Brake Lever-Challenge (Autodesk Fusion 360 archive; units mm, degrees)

design "Brake Lever Challenge" references "Washer DIN 9021 - 6.4 Steel 100 HV Plain", "Broached Hexagon Socket Head Cap Screw ASME B18.3.1M - M6x1 x 20 Steel Grade 2 Plain"
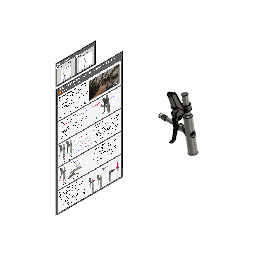
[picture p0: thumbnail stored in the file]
part number: Brake Position
description: Part Number
part number: Brake_Lever
part number: Main Body
part number: Lever
part number: Clamp LHS
description: Broached Hexagon Socket Head Cap Screw ASME B18.3.1M - M5x0.8 x 25
part number: BSHCS ASME B18.3.1M - M5x0.8 x 25 Steel Grade 2 Plain
part number: Clamp RHS
part number: Clamp
sketch "Main Body" plane through (0, 0, 0) normal (0, 1, 0) x axis (1, 0, 0)
  line L1 (-37.3344, -211.7337) -> (0, 0)
  line L2 (0, -10.5441) -> (0, 10.5441)
  line L3 (-16.2493, 2.8652) -> (0, 0)
  line L4 (-39.8655, -131.0687) -> (-16.2493, 2.8652)
  line L5 (-35.6069, -137.1506) -> (-39.8655, -131.0687)
  line L6 (-48.4134, -209.7801) -> (-35.6069, -137.1506)
  line L7 (-37.3344, -211.7337) -> (-48.4134, -209.7801)
  point P1 (0, 0)
  point P2 (0, 0)
  point P3 (-37.3344, -211.7337)
  point P6 (-16.2493, 2.8652)
  point P7 (-39.8655, -131.0687)
  coincident P1 P2
  midpoint P2 L2
  vertical L2
  perpendicular L1 L3
  perpendicular L3 L4
  perpendicular L6 L7
  parallel L1 L6
  dimension "d2" angle L1 L2 = 10
  dimension "d3" distance P2 P3 = 215
  dimension "d4" = 33
  dimension "d5" distance P6 P7 = 136
  dimension "d6" = 22.5
  dimension "d7" angle L4 L5 = 45
revolve "Revolve1" sketch "Main Body" AlongAngle 360
sketch "Mount Solid" plane through (0, 0, 0) normal (0, 1, 0) x axis (1, 0, 0)
  line L1 (-48.4134, -209.7801) -> (-26.2553, -213.6872)
  line L2 (-16.2493, 2.8652) -> (16.2493, -2.8652)
  line L3 (-37.3344, -211.7337) -> (0, 0)
  line L4 (-58.0236, -73.8606) -> (-13.0236, -73.8606)
  line L5 (-58.0236, -61.3606) -> (-13.0236, -61.3606)
  line L6 (-58.0236, -73.8606) -> (-58.0236, -61.3606)
  line L7 (-13.0236, -73.8606) -> (-13.0236, -61.3606)
  point P1 (0, 0)
  point P6 (0, 0)
  point P7 (-37.3344, -211.7337)
  point P8 (-13.0236, -73.8606)
  point P9 (-58.0236, -73.8606)
  point P12 (-58.0236, -73.8606)
  point P10 (-13.0236, -61.3606)
  coincident P1 P6
  midpoint L1 P7
  coincident L3 P8
  horizontal L4
  parallel L4 L5
  perpendicular L5 L6
  vertical P9 P12
  vertical P8 P10
  coincident P9 P12
  dimension "d9" distance L2 P8 = 75
  dimension "d10" distance P8 P9 = 45
  dimension "d11" = 25
revolve "Revolve2" sketch "Mount Solid" AlongAngle 360
sketch "Mount Hole" plane through (0, 0, 0) normal (0, 1, 0) x axis (1, 0, 0)
  line L1 (-58.0236, -61.3606) -> (-58.0236, -86.3606)
  line L2 (11.9764, -73.8606) -> (-58.0236, -73.8606)
  line L3 (-53.0236, -63.3606) -> (-58.0236, -63.3606)
  line L4 (-53.0236, -65.8606) -> (-53.0236, -63.3606)
  line L5 (-13.0236, -65.8606) -> (-53.0236, -65.8606)
  line L6 (-13.0236, -63.3606) -> (-13.0236, -65.8606)
  line L7 (11.9764, -63.3606) -> (-13.0236, -63.3606)
  line L8 (11.9764, -73.8606) -> (11.9764, -63.3606)
  point P4 (-58.0236, -73.8606)
  point P5 (-58.0236, -73.8606)
  point P7 (-58.0236, -63.3606)
  point P11 (-13.0236, -63.3606)
  point P13 (11.9764, -73.8606)
  point P6 (11.9764, -73.8606)
  point P8 (-53.0236, -63.3606)
  point P9 (-53.0236, -65.8606)
  point P10 (-13.0236, -65.8606)
  coincident L1 P4
  coincident P4 P5
  perpendicular L1 L2
  coincident L1 P7
  perpendicular L1 L3
  midpoint L1 P4
  perpendicular L3 L4
  perpendicular L4 L5
  perpendicular L5 L6
  coincident L3 P11
  perpendicular L6 L7
  coincident L2 P13
  perpendicular L2 L8
  coincident P6 P13
  dimension "d15" = 21
  dimension "d16" distance P7 P8 = 5
  dimension "d17" = 16
  dimension "d18" distance P9 P10 = 40
  dimension "d19" distance P5 P6 = 70
revolve "Revolve3" sketch "Mount Hole" AlongAngle 360
fillet "Fillet2" radius 10
sketch "Main Body" plane through (0, 0, 0) normal (0, 1, 0) x axis (1, 0, 0)
  line L1 (-13.0236, -63.3606) -> (-13.0236, -84.3606)
  line L2 (-148.0236, -73.8606) -> (-9.0236, -73.8606)
  line L3 (-9.0236, -79.8606) -> (-9.0236, -73.8606)
  line L4 (-58.0236, -79.8606) -> (-9.0236, -79.8606)
  line L5 (-58.0236, -63.3606) -> (-58.0236, -84.3606)
  line L6 (-58.0236, -81.3606) -> (-58.0236, -79.8606)
  line L7 (-121.0236, -81.3606) -> (-58.0236, -81.3606)
  line L8 (-121.0236, -82.3606) -> (-121.0236, -81.3606)
  line L9 (-136.0236, -82.3606) -> (-121.0236, -82.3606)
  line L10 (-136.0236, -81.3606) -> (-136.0236, -82.3606)
  line L11 (-148.0236, -81.3606) -> (-136.0236, -81.3606)
  line L12 (-148.0236, -73.8606) -> (-148.0236, -81.3606)
  point P6 (-13.0236, -73.8606)
  point P8 (-58.0236, -79.8606)
  point P11 (-58.0236, -81.3606)
  point P12 (-121.0236, -81.3606)
  point P4 (-9.0236, -73.8606)
  point P5 (-148.0236, -73.8606)
  point P13 (-121.0236, -82.3606)
  point P14 (-136.0236, -82.3606)
  point P15 (-136.0236, -81.3606)
  point P16 (-148.0236, -81.3606)
  perpendicular L1 L2
  coincident L1 P6
  midpoint L1 P6
  coincident L2 P6
  perpendicular L2 L3
  perpendicular L3 L4
  coincident P8 L5
  coincident L5 P11
  perpendicular L5 L7
  perpendicular L7 L8
  perpendicular L8 L9
  perpendicular L7 L10
  perpendicular L10 L11
  perpendicular L2 L12
  coincident P12 L11
  dimension "d25" distance L1 P4 = 4
  dimension "d26" = 12
  dimension "d28" distance P4 P5 = 139
  dimension "d33" = 17
  dimension "d35" distance P13 P14 = 15
  dimension "d36" distance P15 P16 = 12
  dimension "d37" = 15
revolve "Revolve1" sketch "Main Body" AlongAngle 360
as_built_joint "As-built1" OffsetX 0 OffsetY 0 OffsetZ 0 AngleZ 0 RotateMinimum 0 RotateMaximum 90
thread "Thread1" ThreadOffset 0 ThreadLength 12
sketch "Flats" plane through (-136.0236, 0, 0) normal (-1, 0, 0) x axis (0, -1, 0)
  line L1 (4, 81.3606) -> (-4, 81.3606)
  line L2 (4, 66.3606) -> (-4, 66.3606)
  line L3 (3.2289, 73.8606) -> (0, 73.8606)
  circle C1 centre (0, 73.8606) radius 8.5
  circle C2 centre (0, 73.8606) radius 7.425
  circle C3 centre (0, 73.8606) radius 8.5
  point P4 (-4, 81.3606)
  point P5 (4, 81.3606)
  point P6 (-4, 66.3606)
  point P7 (4, 66.3606)
  point P3 (0, 73.8606)
  point P8 (0, 73.8606)
  coincident C3 P4
  coincident C3 P5
  horizontal L1
  coincident C3 P6
  coincident C1 P7
  horizontal L2
  coincident P3 P8
  parallel L2 L3
  symmetric L1 L2 L3
  dimension "d38" distance L1 L2 = 15
extrude "Extrude1" cut sketch "Flats" profile of C1 C3 L1 L2 to an object
hole "Hole1" HoleDepth 19 HoleDiameter 5.035 TipAngle 118
sketch "Sketch1" plane through (-13.0236, 0, 0) normal (1, 0, 0) x axis (0, 1, 0)
  circle C1 centre (0, 73.8606) radius 8
  circle C2 centre (0, 73.8606) radius 10.5
  circle C3 centre (0, 73.8606) radius 10.5
  circle C4 centre (0, 73.8606) radius 6
  concentric C1 C3
  concentric C3 C4
  dimension "d46" diameter C3 = 21
  dimension "d47" diameter C4 = 12
extrude "Extrude1" new body sketch "Sketch1" along normal blind 5
as_built_joint "As-built2" OffsetX 0 OffsetY 0 OffsetZ 0 AngleZ 0
copy_paste "CopyPaste2"
joint "Assemble" alignAngle 0 alignOffsetX 0 alignOffsetY 0 alignOffsetZ 0
step "Washer"
joint "Assemble" alignAngle 0 alignOffsetX 0 alignOffsetY 0 alignOffsetZ 0
step "Screw"
joint "Assemble" alignAngle 0 alignOffsetX 0 alignOffsetY 0 alignOffsetZ 0
base_feature "Base Feature1"
base_feature "Base Feature1"
base_feature "Base Feature1"
base_feature "Base Feature1"
base_feature "Base Feature1"
as_built_joint "As-built1" OffsetX 0 OffsetY 0 OffsetZ 0 AngleZ 0
as_built_joint "As-built1"
as_built_joint "As-built2"
as_built_joint "As-built1"
as_built_joint "As-built3" OffsetX 0 OffsetY 0 OffsetZ 0 AngleZ 0 RotateMinimum 0 RotateMaximum 20
joint "Assemble" alignAngle 180 named "Brake_angle" alignOffsetX 0 alignOffsetY 0 alignOffsetZ 0 named "Brake_height"
copy_paste "CutPaste"
as_built_joint "As-built2"
position "Position1"
work_plane "WorkPlane1" AlongDistance -220 ExtraOffset 0
canvas "Canvas3"
canvas "Canvas4"
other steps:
thread "Thread2" ThreadOffset 0 ThreadDepth 7.4
create_component "CreateComponent1"
create_component "CreateComponent2"
create_component "CreateComponent3"
joint_origin "JointOrigin1"
joint_origin "JointOrigin1"
joint_origin "JointOrigin2"
create_component "CreateComponent1"
create_component "CreateComponent2"
create_component "CreateComponent3"
create_component "CreateComponent1"
create_component "CreateComponent2"
create_component "CreateComponent1"
create_component "CreateComponent4"
remove_instance "RemoveInstance1"
joint_origin "JointOrigin3"
joint_origin "JointOrigin4"

design "Broached Hexagon Socket Head Cap Screw ASME B18.3.1M - M6x1 x 20 Steel Grade 2 Plain"
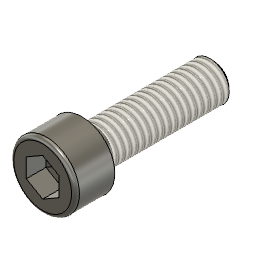
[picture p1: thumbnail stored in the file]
description: Broached Hexagon Socket Head Cap Screw ASME B18.3.1M - M6x1 x 20
part number: BSHCS ASME B18.3.1M - M6x1 x 20 Steel Grade 2 Plain
parameter "adsk_nomlen" = 20
parameter "adsk_headh" = 6
parameter "adsk_headdia" = 10
parameter "adsk_nomdia" = 6
parameter "adsk_philwidth" = 5
parameter "adsk_phildepth" = 3
parameter "adsk_thrlen" = 18.1731
parameter "adsk_startlen" = 0.6135
parameter "adsk_endpointdia" = 4.7731
sketch "Sketch1" plane through (0, 0, 0) normal (0, 1, 0) x axis (1, 0, 0)
  line L1 (-3, 20) -> (-3, 0)
  line L2 (0, 20) -> (-3, 20)
  line L3 (0, -6) -> (0, 20)
  line L4 (-5, 0) -> (-3, 0)
  line L5 (-5, -6) -> (-5, 0)
  line L6 (0, -6) -> (-5, -6)
  point P1 (0, 0)
  point P4 (0, 20)
  point P7 (0, -6)
  point P5 (-5, 0)
  perpendicular L1 L2
  collinear P1 P4 P7
  perpendicular L1 L4
  coincident P1 L4
  vertical L3
  coincident L3 P7
  perpendicular L3 L6
  dimension "d101" distance P1 L2 = 20 (= "adsk_nomlen")
  dimension "d102" distance P5 L6 = 6 (= "adsk_headh")
  dimension "d109" = 10 (= "adsk_headdia")
  dimension "d110" = 6 (= "adsk_nomdia")
revolve "Revolve1" sketch "Sketch1" AlongAngle 360
work_plane "WorkPlane1" AlongDistance 6 (= "adsk_headh")
sketch "Sketch6" plane through (0, 0, 6) normal (0, 0, 1) x axis (1, 0, 0)
  line L1 (2.5, -1.4434) -> (0, -2.8868)
  line L2 (2.5, 1.4434) -> (2.5, -1.4434)
  line L3 (0, 2.8868) -> (2.5, 1.4434)
  line L4 (-2.5, 1.4434) -> (0, 2.8868)
  line L5 (-2.5, -1.4434) -> (-2.5, 1.4434)
  line L6 (0, -2.8868) -> (-2.5, -1.4434)
  point P1 (0, 0)
  point P8 (0, 0)
  coincident P1 P8
  vertical L2
  dimension "d111" distance L2 L5 = 5 (= "adsk_philwidth")
extrude "Extrude1" cut sketch "Sketch6" no distance stored
extrude "Extrude2" cut of existing geometry no distance stored taper -85
thread "Thread3" ThreadOffset 0 ThreadLength 18.1731 (= "min(adsk_thrlen; adsk_nomlen - 0.001 mm)")
fillet "Fillet4" radius 0.6 (= "adsk_nomdia * 0.1")
sketch "Sketch7" plane through (0, 0, 0) normal (0, 1, 0) x axis (1, 0, 0)
  line L1 (-3.06, 19.3866) -> (-3.06, 20)
  line L2 (-2.3865, 20) -> (-3.06, 19.3866)
  line L3 (0, -6) -> (0, 20)
  line L4 (0, 20) -> (-3.06, 20)
  point P5 (0, 20)
  point P7 (0, 20)
  point P4 (-2.3865, 20)
  point P3 (-3.06, 19.3866)
  coincident P5 P7
  perpendicular L3 L4
  coincident P4 L4
  perpendicular L1 L4
  dimension "d104" distance P4 L3 = 2.3866 (= "adsk_endpointdia / 2")
  dimension "d105" distance L1 P7 = 3.06 (= "adsk_nomdia * 0.51")
  dimension "d106" distance P3 L4 = 0.6135 (= "adsk_startlen")
revolve "Revolve3" sketch "Sketch7" AlongAngle 360
joint_origin "JointOrigin2" OffsetX 0 OffsetY 0 OffsetZ 0 AngleZ 0

design "Washer DIN 9021 - 6.4 Steel 100 HV Plain"
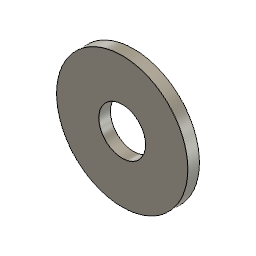
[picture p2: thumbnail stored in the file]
description: Washer DIN 9021 - 6.4
part number: DIN 9021 - 6.4 Steel 100 HV Plain
parameter "adsk_woutdia" = 18
parameter "adsk_windia" = 6.4
parameter "adsk_wthick" = 1.6
sketch "Sketch1" plane through (0, 0, 0) normal (0, 0, 1) x axis (1, 0, 0)
  circle C1 centre (0, 0) radius 9
  circle C2 centre (0, 0) radius 3.2
  point P1 (0, 0)
  point P2 (0, 0)
  point P3 (0, 0)
  coincident P1 P2
  coincident P1 P3
  dimension "d4" diameter C1 = 18 (= "adsk_woutdia")
  dimension "d5" diameter C2 = 6.4 (= "adsk_windia")
extrude "Extrude1" new body sketch "Sketch1" along normal blind 1.6 (= "adsk_wthick")
joint_origin "JointOrigin4" OffsetX 0 OffsetY 0 OffsetZ 0 AngleZ 0
joint_origin "JointOrigin6" OffsetX 0 OffsetY 0 OffsetZ 1.6 (= "adsk_wthick") AngleZ 0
